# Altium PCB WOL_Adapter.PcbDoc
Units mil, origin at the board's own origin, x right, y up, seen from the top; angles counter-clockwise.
Board outline 2890 x 2280 mil, 4 copper layers (Top Layer, Mid-Layer 1, Mid-Layer 2, Bottom Layer), stack 37.4 mil thick; 48 components, 33 nets, 119 pads, 42 vias.
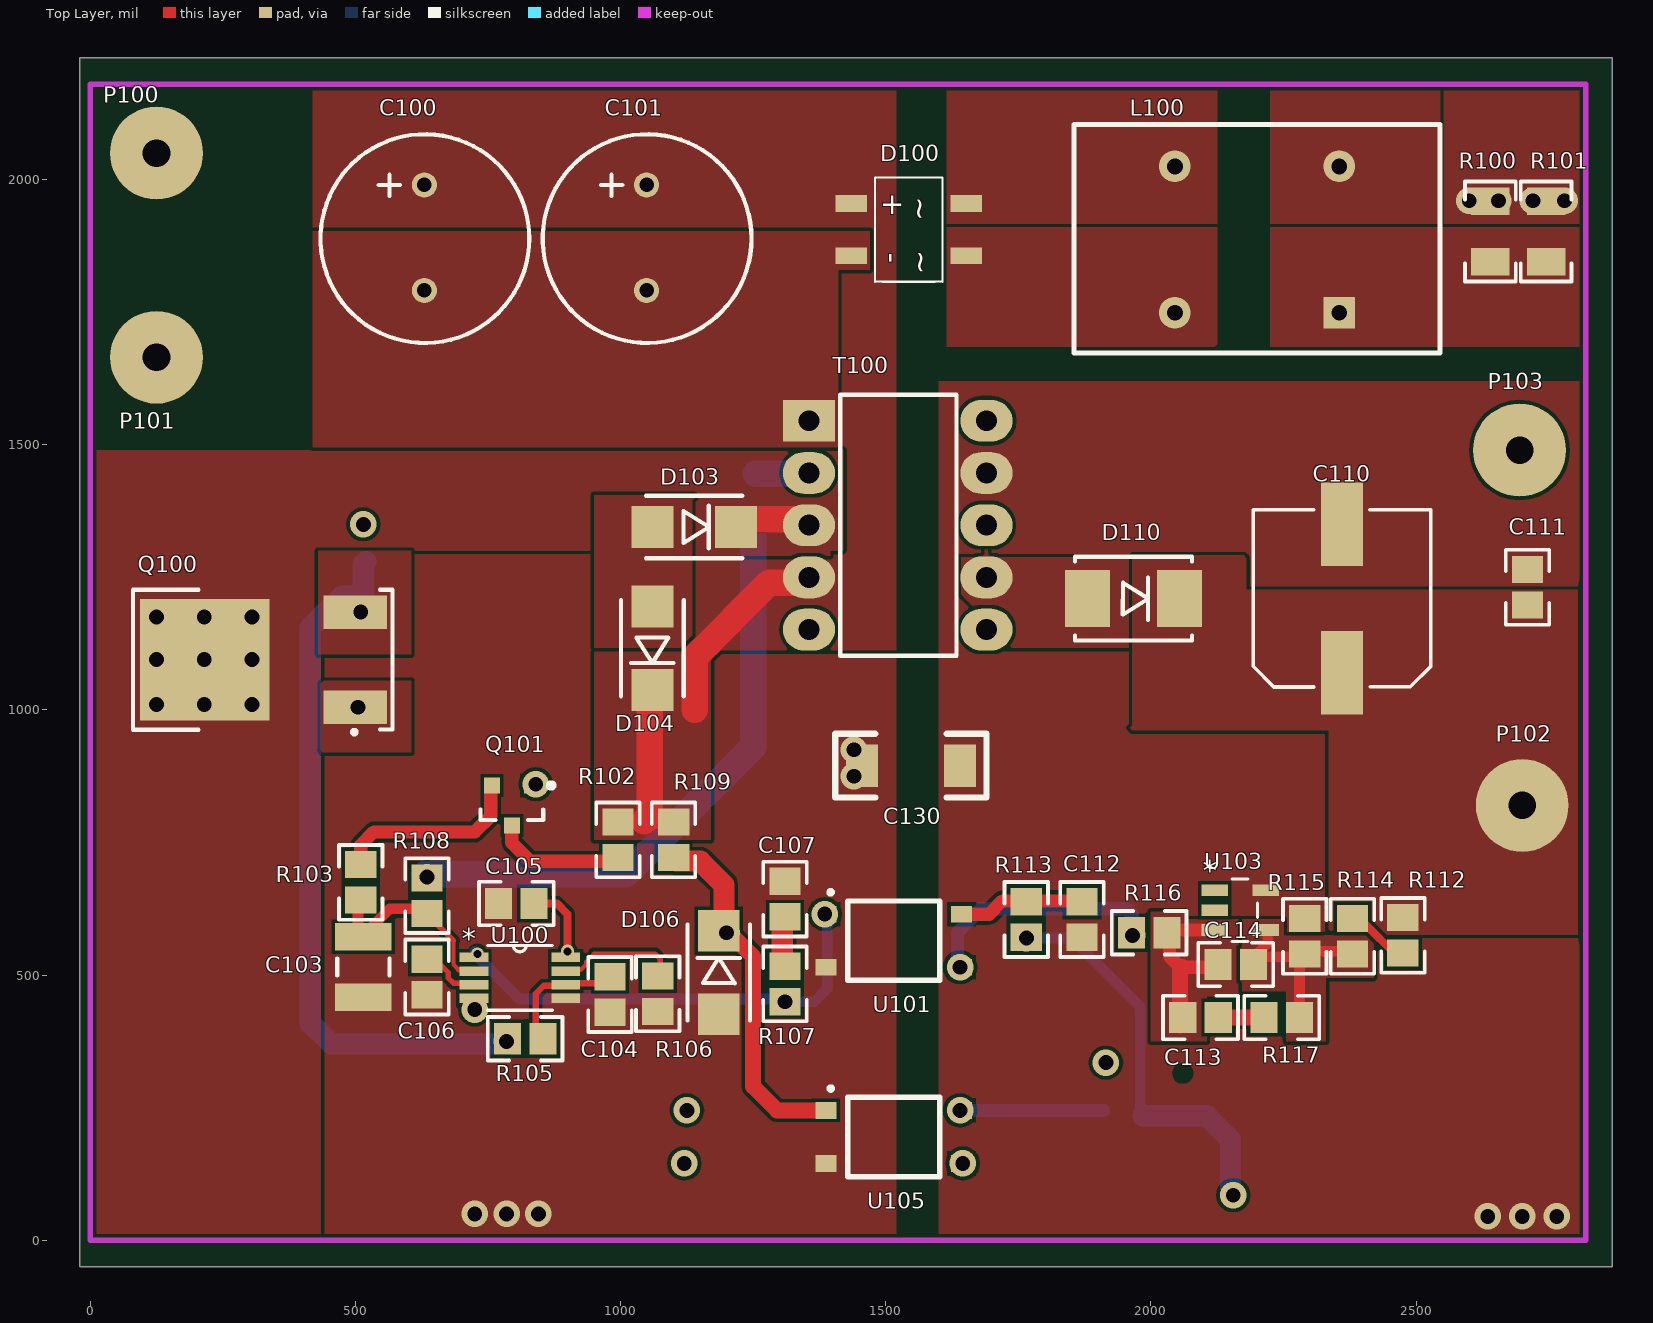
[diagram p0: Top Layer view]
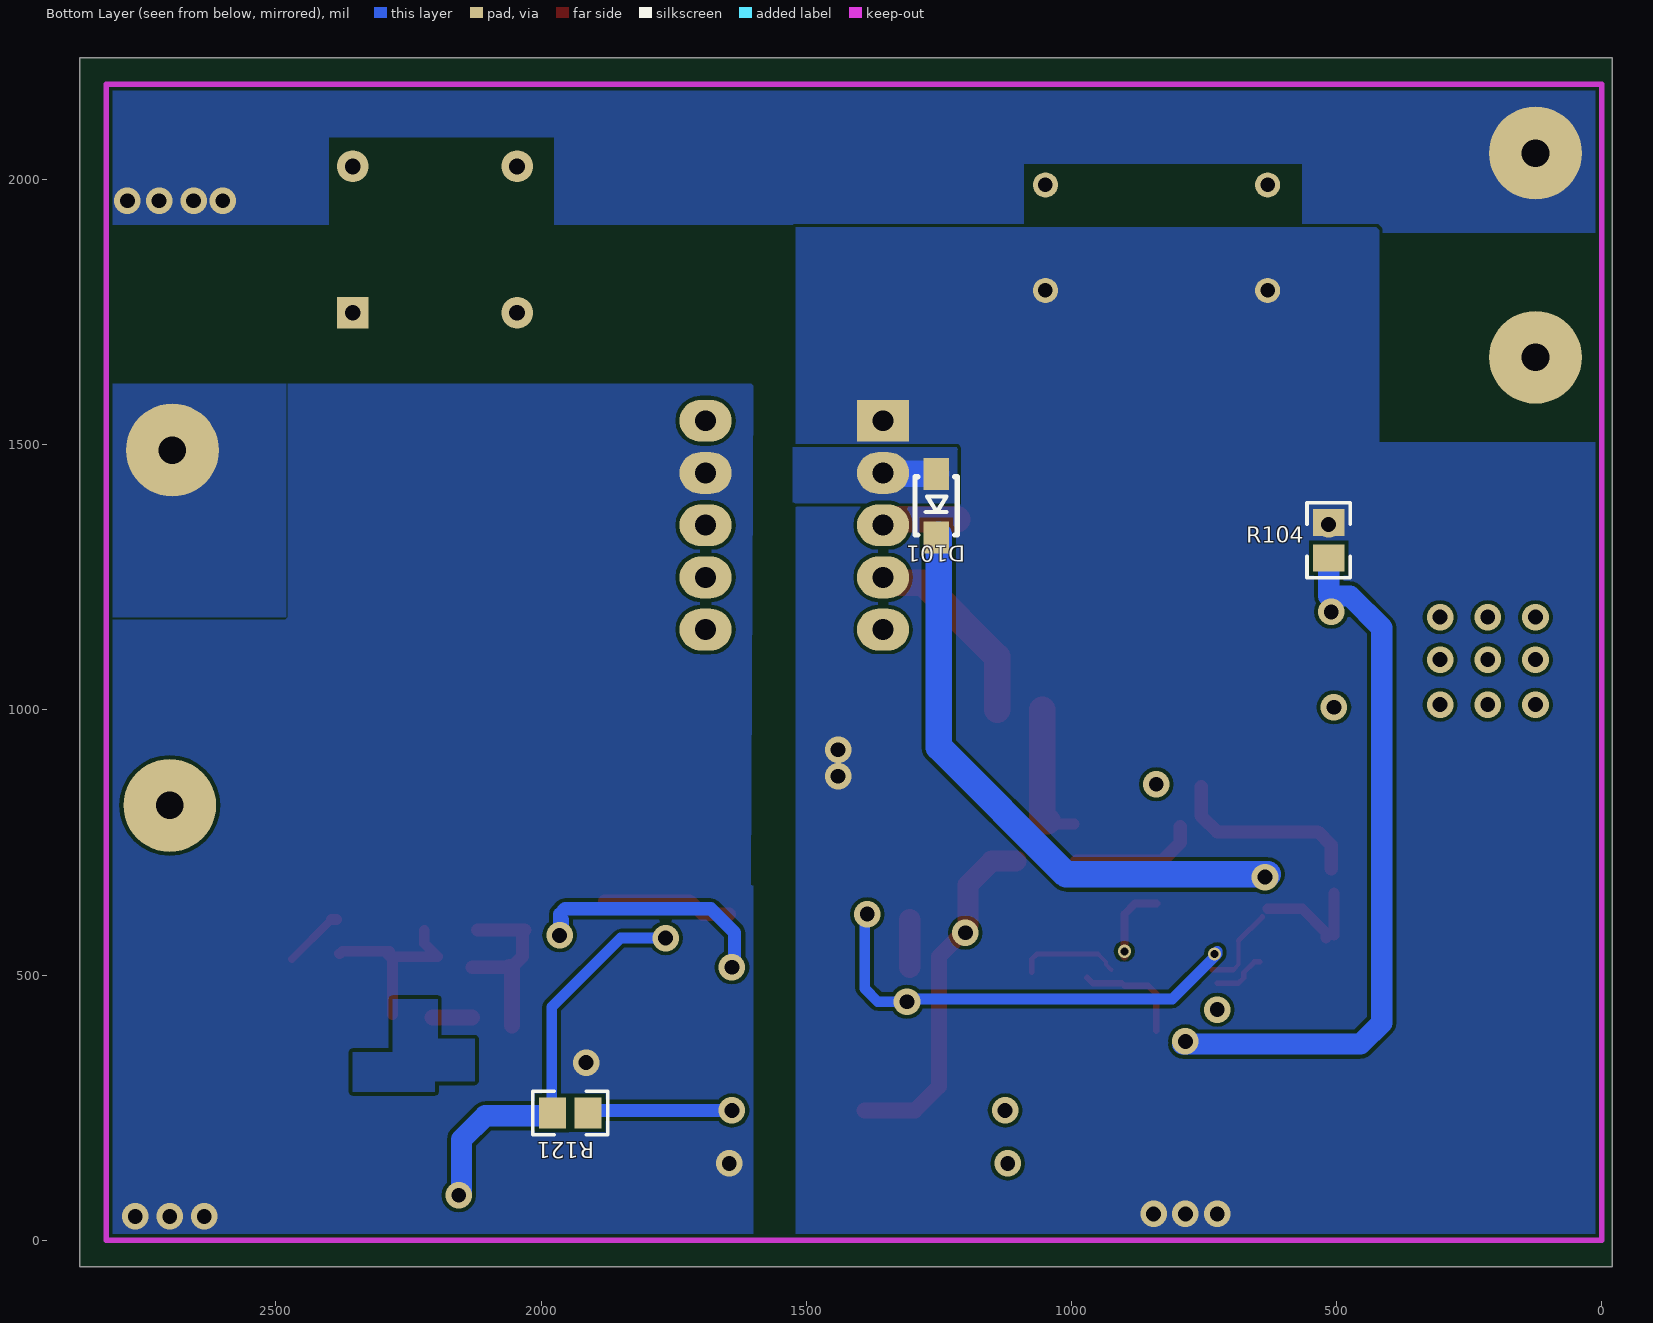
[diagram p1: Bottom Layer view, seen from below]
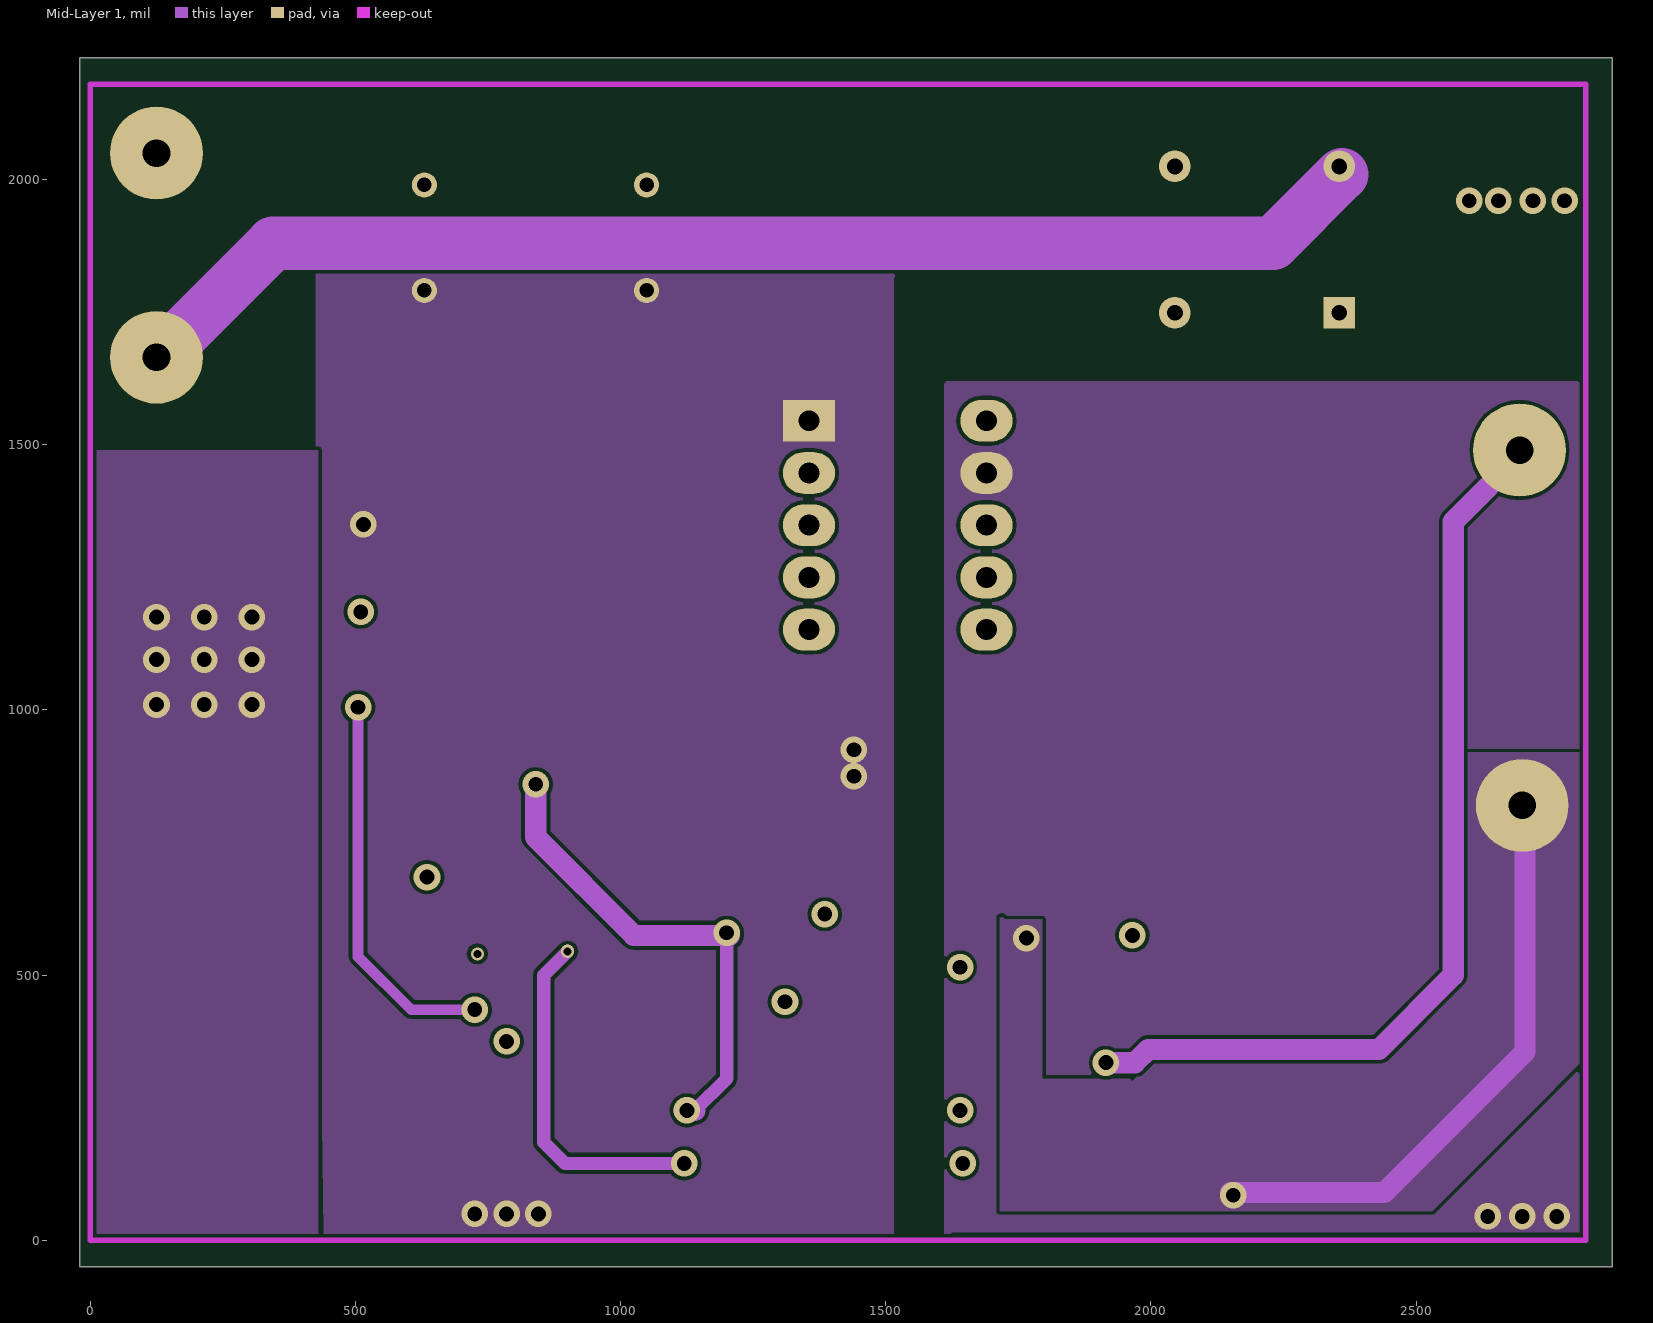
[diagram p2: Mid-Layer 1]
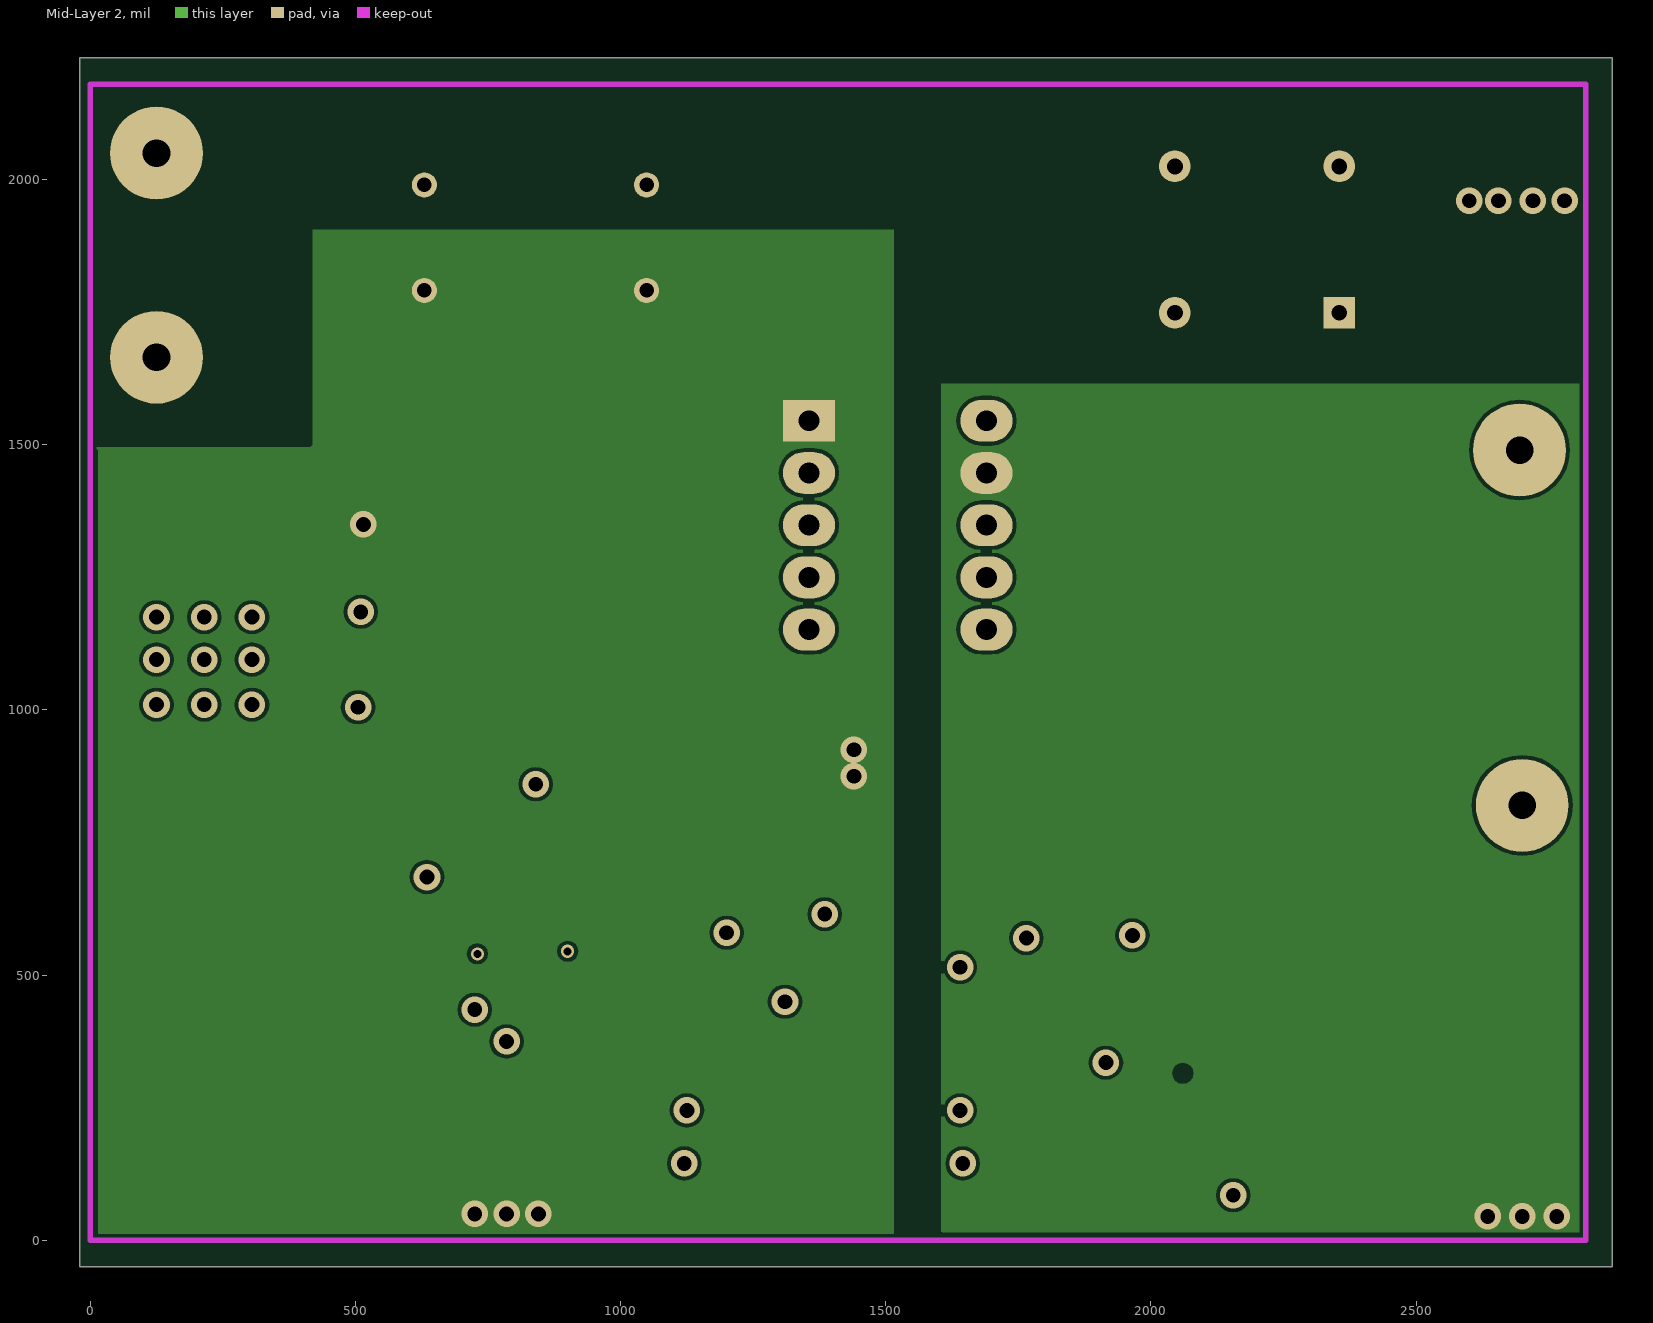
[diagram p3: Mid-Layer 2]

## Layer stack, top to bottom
Top Layer: signal copper 2
Dielectric: prepreg 6, FR-4, Dk 4.8
Mid-Layer 1: signal copper 1.4
Dielectric: prepreg 12.6, FR-4, Dk 4.8
Mid-Layer 2: signal copper 1.4
Dielectric: core 12.6, FR-4, Dk 4.8
Bottom Layer: signal copper 1.4

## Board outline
-20,-50 2870,-50 2870,2230 -20,2230

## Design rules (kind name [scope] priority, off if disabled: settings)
Clearance [All] p1: gap=7
Clearance U100 [(InComponent('U100'))] p2: gap=7
ComponentClearance [All] p1: gap=10 collisioncheckmode=3 verticalgap=10
ComponentClearance ComponentClearance_1 [All] p2: gap=10 collisioncheckmode=0 verticalgap=10
DiffPairsRouting DiffPairsRouting_1 [All] p2: maxlimit=10 minlimit=10 mostfreqgap=10 maxuncoupledlength=500
FanoutControl Fanout_LCC [IsLCC] p1: bgadir=Out bgaviamode=Centered fanoutstyle=Auto fanoutdirection=Alternating viagrid=1 // Fanout_LCC (Default Rule)
FanoutControl Fanout_BGA [IsBGA] p2: bgadir=Out bgaviamode=Centered fanoutstyle=Auto fanoutdirection=Alternating viagrid=1 // Fanout_BGA (Default Rule)
FanoutControl Fanout_Default [All] p4: bgadir=Out bgaviamode=Centered fanoutstyle=Auto fanoutdirection=Alternating viagrid=1 // Fanout_Default (Default Rule)
FanoutControl Fanout_Small [(CompPinCount < 5)] p5: bgadir=Out bgaviamode=Centered fanoutstyle=Auto fanoutdirection=OutThenIn viagrid=1 // Fanout_Small (Default Rule)
FanoutControl Fanout_BGA_1 [IsBGA] p6: bgadir=Out bgaviamode=Centered fanoutstyle=Auto fanoutdirection=Alternating viagrid=1 // Fanout_BGA (Default Rule)
FanoutControl Fanout_LCC_1 [IsLCC] p7: bgadir=Out bgaviamode=Centered fanoutstyle=Auto fanoutdirection=Alternating viagrid=1 // Fanout_LCC (Default Rule)
FanoutControl Fanout_SOIC_1 [IsSOIC] p8: bgadir=Out bgaviamode=Centered fanoutstyle=Auto fanoutdirection=Alternating viagrid=1 // Fanout_SOIC (Default Rule)
FanoutControl Fanout_Small_1 [(CompPinCount < 5)] p9: bgadir=Out bgaviamode=Centered fanoutstyle=Auto fanoutdirection=OutThenIn viagrid=1 // Fanout_Small (Default Rule)
FanoutControl Fanout_Default_1 [All] p10: bgadir=Out bgaviamode=Centered fanoutstyle=Auto fanoutdirection=Alternating viagrid=1 // Fanout_Default (Default Rule)
Height Height_1 [All] p2: minheight=0 maxheight=1000 prefheight=500
HoleSize [All] p1: absolutevalues=TRUE maxlimit=251 minlimit=8 maxpercent=80.000 minpercent=20.000
HoleSize HoleSize_1 [All] p2: absolutevalues=TRUE maxlimit=100 minlimit=1 maxpercent=80.000 minpercent=20.000
LayerPairs LayerPairs_1 [All] p2: enforce=TRUE
MinimumAnnularRing [All] p1: minimumring=5
PasteMaskExpansion PasteMaskExpansion_1 [All] p2: expansion=0
PlaneClearance PlaneClearance_1 [All] p2: clearance=20
PolygonConnect [All] p1: connectstyle=Direct reliefconductorwidth=8 reliefentries=4 polygonreliefangle="90 Angle"
PolygonConnect PolygonConnect_1 [All] p2: connectstyle=Relief reliefconductorwidth=10 reliefentries=4 polygonreliefangle="90 Angle"
RoutingPriority RoutingPriority_1 [All] p2: routingpriority=0
RoutingTopology RoutingTopology_1 [All] p2: topology=Shortest
RoutingVias [All] p1: holewidth=25 width=15 viastyle="Through Hole" minholewidth=5 minwidth=5 maxholewidth=28 maxwidth=50
ShortCircuit ShortCircuit_1 [All] p2: allowed=FALSE
SolderMaskExpansion [All] p1: expansion=3
SolderMaskExpansion SolderMaskExpansion_1 [All] p2: expansion=4
TestPointUsage [All] p1: valid=0 allowmultiple=FALSE
TestPointUsage TestPointUsage_1 [All] p2: valid=0 allowmultiple=FALSE
Testpoint [All] p1: side=15 testpointundercomponent=TRUE minsize=40 maxsize=100 preferedsize=60 minholesize=0 maxholesize=40 preferedholesize=32 testpointgrid=1 style=1023 order=0-112345678
Testpoint Testpoint_1 [All] p2: side=15 testpointundercomponent=TRUE minsize=40 maxsize=100 preferedsize=60 minholesize=0 maxholesize=40 preferedholesize=32 testpointgrid=1 style=1023 order=0-112345678
UnRoutedNet UnRoutedNet_1 [All] p2:
Width [All] p1: maxlimit=100 minlimit=8 preferedwidth=8 minimp=50.000000 maximp=50.000000 favimp=50.000000
13 further rules are at their usual default settings.

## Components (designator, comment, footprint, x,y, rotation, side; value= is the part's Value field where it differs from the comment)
C100 "UVR2W4R7MPD" "10mm th cap" 631,1810 r90 top
C101 "UVR2W4R7MPD" "10mm th cap" 1050,1810 r90 top
C103 "C3225X7R1E106M" 1210 515,515.39 r270 top
C104 "C2012X7R1H102K" 0805 980,463.46 r270 top
C105 "C2012X7R2A223K" 0805 803.46,635 r180 top
C106 "C2012X5R1E105K" 0805 635,496.54 r270 top
C107 "CC0805KRX7R9BB273" 0805 1310,643.46 r90 top
C110 "EEV-FK0J471P" SM_RADIAL_F 2360,1210.24 r270 top
C111 "C2012X5R0J226M" 0805 2710,1231.54 r90 top
C112 "C2012X7R1E474K" 0805 1870,605 r270 top
C113 "GRM21BR71H473KA01L" 0805 2093.46,420 r180 top
C114 "GQM2195C1H101JB01D" 0805 2160,520 r180 top
C130 "1000pF" 1808 1455,895 r0 top
D100 "DIODE-BRIDGE1" bridge 1435,1955 r0 top
D101 "1N4148W-7-F" SOD-123 1255,1385 r270 bottom
D103 "CMZ5938B" SMA 1138.74,1345 r0 top
D104 "10MQ100NTRPBF" SMA 1060,1116.26 r270 top
D106 "36V" SMA 1185,505 r90 top
D110 "B2100-13" SMB 1967.01,1210 r0 top
L100 "CM CHOKE" BU9S 2355,1749 r180 top
P100 "LIVE" PAD175#1 125,2050 r0 top
P101 "NEUTRAL" PAD175#2 125,1635 r0 top
P102 "Vout+" PAD175#1 2700,820 r0 top
P103 "Vout-" PAD175#1 2695,1490 r0 top
Q100 "SPD06N80C3" DPAK 304.33,1094.76 r180 top
Q101 "Manufacturer_PN" sot-23 795,820 r270 top
R100 "CRCW1206-20R0FRT1" 1206 2640,1902.09 r90 top
R101 "CRCW1206-20R0FRT1" 1206 2745,1902.09 r90 top
R102 "CRCW08051M00FKEA" 0805 995,755 r270 top
R103 "CRCW0805200kFKEA" 0805 510,675 r270 top
R104 "CRCW08052R21FNEA" 0805 515,1320 r90 bottom
R105 "CRCW0805499RFKEA" 0805 820,380 r0 top
R106 "CRCW080582k5FKEA" 0805 1070,465 r270 top
R107 "CRCW08051k00FKEA" 0805 1310,483.46 r90 top
R108 "CRCW080530R1FKEA" 0805 635,650 r270 top
R109 "CRCW080510M0FKEA" 0805 1100,755 r270 top
R112 "CRCW080549R9FKEA" 0805 2475,575 r270 top
R113 "CRCW080510R0FKEA" 0805 1765,605 r90 top
R114 "CRCW080563k4FKEA" 0805 2380,573.46 r270 top
R115 "CRCW080520k5FKEA" 0805 2290,573.46 r90 top
R116 "CRCW0805499RFKEA" 0805 1996.54,580 r0 top
R117 "CRCW0805499RFKEA" 0805 2246.54,420 r0 top
R121 "CRCW080510k0FKEA" 0805 1945,240 r180 bottom
T100 "XFMR-PA2685NL" PA2685NL 1355,1545.28 r0 top
U100 "LM5021MM" MUA08A 810,495 r0 top
U101 "PS2501L-1H" FOD121 1515,565 r0 top
U103 "LMV431M5" MF05A 2168,622.5 r0 top
U105 "FODM121" FOD121 1515,195 r0 top

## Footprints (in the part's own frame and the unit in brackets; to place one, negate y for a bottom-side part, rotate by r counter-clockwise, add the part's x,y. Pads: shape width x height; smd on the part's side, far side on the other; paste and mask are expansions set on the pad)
"10mm th cap" [mm]
  round 1.2 hole 0.7: 1(4.572,0.025) 2(-0.483,0.025)
  silkscreen extent -3,-5 7,5
0805 [mm] "0805 from SM-752 data"
  rect 1.3x1.5 smd: 1(-0.85,0) 2(0.85,0)
  silkscreen extent -1.79,-1.04 1.79,1.04, body extent -1.1,-0.72 1.1,0.72, height 1.1
1206 [mm] "1206 from SM-752 data"
  rect 1.3x1.85 smd: 1(-1.45,0) 2(1.45,0)
  silkscreen extent -2.39,-1.22 2.39,1.22, body extent -1.7,-0.9 1.7,0.9, height 1.35
1210 [mm] "1210 from SM-752 data"
  rect 1.3x2.7 smd: 1(-1.45,0) 2(1.45,0)
  silkscreen extent -0.4,-1.25 0.4,1.25, body extent -1.7,-1.35 1.7,1.35, height 1.35
1808 [mil]
  rect 60x80 smd: 1(0,0) 2(185,0)
  silkscreen extent -50,-60 235,60
bridge [mm]
  rect 1.5x0.8 smd: 1(0,0) 2(0,-2.5) 3(5.5,-2.5) 4(5.5,0)
  silkscreen extent 1.14,-3.76 4.37,1.25
BU9S [mil]
  rect 60x60 hole 30: 1(0,0)
  round 60 hole 30: 2(0,-276) 3(310,-276) 4(310,0)
  silkscreen extent -190,-355 500,76
DPAK [mm] "D-PAK, 3-Pads, Body 6.2x6.7mm (max), IPC Medium Density_modified 2008-05-02 to match OnSemi land pattern"
  rect 3.05x1.6 smd: 1(-4.97,2.28) 3(-4.97,-2.28)
  rect 6.2x5.8 smd: 4(2.25,0)
  silkscreen extent -6.75,-3.35 5.68,3.55, body extent -2.1,-3.35 4.1,3.35, height 2.39
FOD121 [mm] "Fairchild OptoCoupler"
  rect 1x0.8 smd: 1(-3.25,1.27) 2(-3.25,-1.27) 3(3.25,-1.27) 4(3.25,1.27)
  silkscreen extent -3.1,-1.9 2.2,2.39, body extent -3.85,-2.03 3.85,2.03, height 2.3
MF05A [mil]
  rect 50x22 smd: 1(-48,37.5) 2(-48,0) 3(-48,-37.5) 4(48,-37.5) 5(48,37.5)
  silkscreen extent -15,-59 33,59
MUA08A [mil]
  rect 54x18 smd: 1(-86.5,38.39) 2(-86.5,12.8) 3(-86.5,-12.8) 4(-86.5,-38.39) 5(86.5,-38.39) 6(86.5,-12.8) 7(86.5,12.8) 8(86.5,38.39)
  silkscreen extent -61,-61 61,61
PA2685NL [mm] "Pulse PA2685"
  rect 2.5x2 hole 1: 1(0,0)
  oval 2.5x2 hole 1: 2(0,-2.5) 3(0,-5) 4(0,-7.5) 5(0,-10) 6(8.5,-10) 7(8.5,-7.5) 8(8.5,-5) 9(8.5,-2.5) 10(8.5,0)
  silkscreen extent 1.5,-11.25 7.07,1.25
PAD175#1 [mil]
  round 175 hole 52: 1(0,0)
PAD175#2 [mil]
  round 175 hole 52: 1(0,30)
SM_RADIAL_F [mm] "Panasonic F"
  rect 4x2 smd: 1(3.55,0) 2(-3.55,0)
  silkscreen extent -4.25,-4.25 4.24,4.25
SMA [mm] "Molded Diode, 2-Leads, Body 4.3x2.6mm, IPC Medium Density, based on OnSemi component dimensions and land pattern"
  rect 2x2 smd: 1(-2,0) 2(2,0)
  silkscreen extent -2.3,-1.5 2.3,1.5, body extent -2.29,-1.46 2.28,1.46, height 2.27
SMB [mil] "Molded Diode, 2-Leads, Body 5.4x3.6mm, IPC Medium Density, based on OnSemi component dimensions"
  rect 85x107.99 smd: 1(-87.01,0) 2(87.01,0)
  silkscreen extent -110,-79 110,79, body extent -110,-78 110,78, height 96
SOD-123 [mil]
  rect 60x48 smd: 1(-60,0) 2(60,0)
  silkscreen extent -55,-40 55,40
sot-23 [mm] "SOT23, 3-Leads, Body 3.0x2.6mm (max), Pitch 0.95mm, IPC Medium Density, from National MF03A"
  rect 0.76x0.76 smd: 1(-0.955,0.953) 2(-0.955,-0.953) 3(0.955,0)
  silkscreen extent -1.08,-1.5 0.7,2.01, body extent -0.7,-1.52 0.7,1.52, height 1.12

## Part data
C100 C101: library part WB_CAP_POLARIZED, "Polarized Capacitor"
C103 C104 C105 C106 C107 C111 C112 C113 C114: "Capacitor"
C110: "Polarized Capacitor"
C130: library part CAP-1808, "Capacitor Ceramic X7R"
D100: "Diode Bridge"
D101 D110: "Schottky Diode"
D103 D106: library part WB_Zener
D104: library part WB_DIODE, "Diode"
L100: library part "IND-COMMON MODE CHOKE", "coil craft common mode choke"
P100 P101 P102 P103: library part PAD175, "TEST POINT"
Q101: library part MMBTA42, "NPN Transistor"
R100 R101 R102 R103 R104 R105 R106 R107 R108 R109 R112 R113 R114 R115 R116 R117 R121: "Resistor"
T100: library part XFMR-PA1407, "POE TRANSFORMER"
U100: library part LM5021MM-1, "AC-DC Current Mode PWM Controller"
U101 U105: "Full Pitch Mini-Flat Package Transistor Output  Optocoupler"
U103: library part LMV431IM5, "Low-Voltage (1.24V) Adjustable Precision Shunt Regulators"

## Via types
v1: diameter 50, hole 28, Top Layer to Bottom Layer, 40 vias
v2: diameter 25, hole 15, Top Layer to Bottom Layer, 2 vias

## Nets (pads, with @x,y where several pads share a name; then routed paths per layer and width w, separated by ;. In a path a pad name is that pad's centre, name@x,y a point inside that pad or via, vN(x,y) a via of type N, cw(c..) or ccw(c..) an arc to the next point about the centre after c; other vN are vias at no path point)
GND: C100.2 C101.2 C103.2 C104.2 C105.2 C106.2 C107.2 C130.1 D100.2 D106.1 R104.2 R106.2 T100.1 U100.5 U101.2 U105.2
  other v1: 725,50 785,50 845,50 1440,875 1440,925 515,1350
NetC100_1: C100.1 C101.1 D100.1 D104.2 R102.1 R109.1 T100.4 | length 702.1
  Top Layer w20: R102.1@995,785 R109.1@1100,785
  Top Layer w50: 1045,790 1055,800 D104.2@1055,1000 ; 1140,1000 1140,1100 1280,1240 T100.4@1365,1240
NetC103_1: C103.1 R103.2 R108.2 U100.2 | length 381.4
  Top Layer w8: 685,565 685,520 695,510
  Top Layer w10: R108.2@640,610 685,565 ; 695,510 U100.2@735,510
  Top Layer w20: C103.1@505,575 R103.2@505,655 ; C103.1@520,570 520,580 565,625 R108.2@630,625
NetC104_1: C104.1 R105.2 U100.6 | length 205.4
  Top Layer w12: R105.2@840,395 840,465 855,480 U100.6@900,480 ; U100.6@905,485 960,485 C104.1@970,495
NetC105_1: C105.1 U100.8 | length 808.5
  Top Layer w15: C105.1@840,635 880,635 900,615 U100.8@900,535
  Mid-Layer 1 w25: v2(900,545) 855,500 855,185 895,145 v1(1120,145)
NetC106_1: C106.1 U100.3 | length 102.4
  Top Layer w10: C106.1@645,525 655,525 675,505 675,495 685,485 U100.3@725,485
NetC107_1: C107.1 R107.2 | length 90
  Top Layer w40: R107.2@1305,515 C107.1@1305,605
NetC110_1: C110.1 C111.1 D110.2 P102.1 R112.1 R113.1 R121.1 | length 1942.3
  Mid-Layer 1 w40: v1@2150,90 2440,90 2705,355 P102.1@2705,820
  Bottom Layer w15: R121.1@1975,240 2035,240
  Bottom Layer w20: v1(1765,570) 1850,570 1980,440 R121.1@1980,240
  Bottom Layer w40: R121.1@1985,235 2105,235 2150,190 v1@2150,90
  other v1: 2155,85
NetC112_1: C112.1 R113.2 U101.4 | length 252.4
  Top Layer w25: U101.4@1645,615 1695,615 1720,640 C112.1@1880,640 ; R113.2@1760,635 R113.2@1765,630
NetC113_1: C113.1 R117.1 | length 75
  Top Layer w30: C113.1@2130,420 R117.1@2205,420
NetC113_2: C113.2 C114.2 R116.2 U103.3 | length 345.4
  Top Layer w25: R116.2@2030,585 U103.3 ; R116.2@2035,575 2035,535 2055,515 C114.2@2130,515
  Top Layer w30: C113.2@2055,405 2055,510 2060,515
NetC114_1: C114.1 R114.2 R115.1 R117.2 U103.4 | length 366.6
  Top Layer w20: U103.4@2220,585 2220,560 2195,535 R115.1@2285,535 ; R117.2@2280,425 2280,530 R115.1 ; R115.1@2285,545 2375,545 R114.2
NetD100_3: D100.3 L100.4
NetD100_4: D100.4 L100.3
NetD101_1: D101.1 T100.2 | length 105
  Bottom Layer w50: D101.1 T100.2@1360,1445
NetD101_2: D101.2 R108.1 | length 1119.4
  Bottom Layer w50: v1@630,690 1010,690 1250,930 D101.2@1250,1330
  other v1: 635,685
NetD103_1: D103.1 D104.1
NetD103_2: D103.2 Q100.4 T100.3 | length 151.2
  Top Layer w50: D103.2@1215,1360 1345,1360 T100.3@1360,1345
  other v1: 125,1010 215,1010 305,1010 125,1095 215,1095 305,1095 125,1175 215,1175 305,1175
NetD106_2: D106.2 Q101.1 R109.2 U105.1 | length 1567.4
  Top Layer w30: D106.2@1205,580 1250,535 1250,290 1295,245 U105.1@1390,245
  Top Layer w40: R109.2@1105,715 1150,715 1195,670 D106.2@1195,595
  Mid-Layer 1 w25: v1@1140,245 1200,305 v1@1200,570
  Mid-Layer 1 w40: v1@840,865 840,760 1025,575 v1@1205,575 ; v1@1120,245 v1@1140,245
  other v1: 1125,245 1200,580 840,860
NetD110_1: D110.1 T100.7
NetL100_1: L100.1 R100.1 R101.1
NetL100_2: L100.2 P101.1 | length 2404.1
  Mid-Layer 1 w100: P101.1@115,1640 115,1650 345,1880 2230,1880 L100.2@2360,2010
NetP100_1: P100.1 R100.2 R101.2
  other v1: 2600,1960 2655,1960 2720,1960 2780,1960
NetQ100_1: Q100.1 U100.4 | length 741.4
  Mid-Layer 1 w20: v1@505,1010 505,535 605,435 v1@730,435
  other v1: 725,435 505,1005
NetQ100_3: Q100.3 R104.1 R105.1 | length 1328.5
  Bottom Layer w40: R104.1@520,1280 515,1275 515,1215 475,1215 415,1155 415,410 455,370 v1@790,370
  other v1: 785,375 510,1185
NetQ101_2: Q101.2 R103.1 | length 367.8
  Top Layer w25: R103.1@510,700 510,745 535,770 725,770 755,800 Q101.2@755,855
NetQ101_3: Q101.3 R102.2 | length 239.5
  Top Layer w25: Q101.3@795,780 795,750 830,715 R102.2@990,715
NetR106_1: R106.1 U100.7 | length 194.5
  Top Layer w8: 925,510 935,520 935,525 950,540
  Top Layer w10: 950,540 1065,540 1075,530 R106.1@1075,505
NetR107_1: R107.1 U100.1 U101.1 | length 855.6
  Bottom Layer w20: v2@725,545 725,540 810,455 v1@1310,455 ; v1(1310,450) 1365,450 1390,475 v1@1390,615
  other v1: 1385,615
  other v2: 730,540
NetR112_2: R112.2 R114.1 | length 116.1
  Top Layer w15: R114.1@2395,605 R112.2@2470,530
  Top Layer w20: R114.1@2385,605 R114.1@2395,605
NetR116_1: R116.1 U101.3 | length 487.8
  Bottom Layer w25: v1@1635,515 1635,580 1680,625 1955,625 1965,615 v1(1965,575) ; v1@1960,575 1960,605
  other v1: 1640,515
NetR121_2: R121.2 U105.4 | length 279.1
  Bottom Layer w25: v1@1635,235 1645,245 R121.2@1910,245
  other v1: 1640,245
RTN: C110.2 C111.2 C112.2 C130.2 P103.1 R115.2 T100.9 U103.5 U105.3 | length 1769.3
  Mid-Layer 1 w40: v1(1915,335) 1970,335 1995,360 2430,360 2570,500 2570,1355 P103.1@2705,1490
  other v1: 2635,45 2700,45 2765,45 1645,145
pads on no net: T100.5 T100.6 T100.8 T100.10 U103.1 U103.2

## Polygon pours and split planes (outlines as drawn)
GND on Top Layer "GND" (solid, remove dead copper, pour order 1017): 430,1305 430,10 1510,10 1520,0 1520,1105 955,1105 950,1110 950,1305 435,1305
RTN on Top Layer "RTN" (solid, remove dead copper, pour order 1001): 2815,580 2815,5 2810,0 1600,0 1600,1620 2815,1620 2815,1225 2810,1220 2800,1230 2180,1230 2180,1290 2175,1295 1635,1295 1635,1215 1645,1205 1665,1185 1665,1110 1965,1110 1970,1105 1965,1100 1965,965 2340,965 2345,960 2350,955 2350,580 2815,580
NetD110_1 on Top Layer "NetD110_1" (solid, remove dead copper, pour order 1020): 1635,1305 1635,1105 1965,1105 1970,1110 1975,1115 1975,1305 1640,1305
NetC113_2 on Top Layer "NetC113_2" (solid, remove dead copper, pour order 1000): 2000,610 2000,375 2105,375 2105,460 2165,460 2165,605 2065,605 2065,620 2000,620 2000,610
NetC114_1 on Top Layer "NetC100_1" (solid, remove dead copper, pour order 1001): 2170,605 2165,600 2165,470 2255,470 2255,375 2330,375 2330,495 2420,495 2420,575 2250,575 2250,605 2170,605 2165,600
NetL100_1 on Top Layer "NetL100_1" (solid, remove dead copper, pour order 1002): 2225,1910 2225,1685 2815,1685 2810.2,1689.69 2810.2,1910 2225,1910
NetD100_3 on Top Layer "NetD100_3" (solid, remove dead copper, pour order 1003): 1615,1910 1615,1685 2120.1,1685 2125,1689.79 2125,1910 1619.9,1910
NetD100_4 on Top Layer "NetD100_4" (solid, remove dead copper, pour order 1004): 1615,2170 2125,2170 2125,1905 2120.1,1910 1615,1910 1615,2165
NetL100_2 on Top Layer "NetL100_2" (solid, remove dead copper, pour order 1005): 2225,2170 2545,2170 2545,1910 2540.36,1915 2225,1915 2225,2170
NetP100_1 on Top Layer "NetP100_1" (solid, remove dead copper, pour order 1006): 2550,2175 2810,2175 2810,1910 2820,1900 2545,1900 2545,2175 2550,2175
NetC100_1 on Top Layer "NetC100_1" (solid, remove dead copper, pour order 1007): 420,2180 420,1910 1470,1910 1470,2185 1465,2180 420,2180
NetC100_1 on Top Layer "NetC100_1" (solid, remove dead copper, pour order 1008): 950,1110 950,755 1170,755 1170,1110 950,1110
NetD103_1 on Top Layer "NetD103_1" (solid, remove dead copper, pour order 1009): 950,1405 1145,1405 1135,1395 1135,1110 950,1110 950,1405
NetQ100_3 on Top Layer "NetQ100_3" (solid, remove dead copper, pour order 1010): 430,1300 605,1300 605,1105 430,1105 430,1315
NetQ100_1 on Top Layer "NetQ100_1" (solid, remove dead copper, pour order 1011): 440,1055 605,1055 605,920 430,920 435,925 435,1050 440,1055
GND on Top Layer "GND" (solid, remove dead copper, pour order 1014): 420,1905 1470,1905 1470,1830 1410,1830 1410,1490 1405,1495 420,1495 420,1905
NetD103_2 on Top Layer "NetD103_2" (solid, remove dead copper, pour order 1015): 5,1490.02 1425,1490.02 1430,1495 1395,1460.12 1395,1290.68 955,1290.68 945,1300.65 435,1300.65 435,4.98 430,0 0,0 0,1485.03 -5,1490.02
NetD103_2 on Top Layer "NetD103_2" (solid, remove dead copper, pour order 1016): 1290,1495 1420,1495 1420,1295 1415,1300 1300,1300 1300,1490 1295,1495
NetC100_1 on Top Layer "NetC100_1" (solid, remove dead copper, pour order 1018): 952.43,1110 952.43,760 957.45,755 1349.23,755 1349.23,1095 1354.25,1090 1520,1090 1520,2170 420.02,2170 420.02,1915 415,1910 420.02,1905 1474.8,1905 1474.8,1830 1414.52,1830 1414.52,1295 1404.48,1305 947.41,1305 947.41,1120
NetC110_1 on Top Layer "NetC110_1" (solid, remove dead copper, pour order 1000): 1960,1291.49 2175,1291.49 2180,1286.49 2180,1226.49 2805,1226.49 2805,576.49 2345,576.49 2335,586.49 2335,961.49 1965,961.49 1960,966.49 1965,971.49 1965,1286.49
RTN on Mid-Layer 1 "RTN" (solid, remove dead copper, pour order 1024): 1610,1615 1610,10 1615,5 1625,15 2815,15 2815,1610 2805,1620 1615,1620
NetC110_1 on Mid-Layer 1 "NetC100_1" (solid, remove dead copper, pour order 1000): 2595,920 2590,915 2590,490 2570,490 2430,350 2005,350 2005,340 1965,300 1960,305 1795,305 1795,405 1795,605 1725,605 1715,615 1715,105 1715,55 2450,55 2530,55 2715,240 2820,345 2820,920 2590,920
NetD103_2 on Mid-Layer 1 "D103_2" (solid, remove dead copper, pour order 1022): 0,1490 430,1490 430,10 435,5 5,5 5,1490 0,1495
GND on Mid-Layer 1 "GND" (solid, remove dead copper, pour order 1023): 440,10 425,25 425,1825 1515,1825 1520,1820 1515,1815 1515,5 435,5 430,10 420,20 420,1495
GND on Mid-Layer 2 "GND" (solid, remove dead copper, pour order 1025): 5,1495 415,1495 420,1500 420,1905 1515,1905 1515,5 10,5 5,0 15,10 15,1490
RTN on Mid-Layer 2 "RTN" (solid, remove dead copper, pour order 1026): 1605,1615 2810,1615 2810,15 1610,15 1600,5 1605,10 1605,1615
RTN on Bottom Layer "RTN" (solid, remove dead copper, pour order 1031): 1600,1615 1600,5 2815,5 2809.96,10 2809.96,1170 2482.26,1170 2477.22,1175 2477.22,1615 1600,1615 1600,675 1605.04,670
NetD101_1 on Bottom Layer "NetD101_!" (solid, remove dead copper, pour order 1027): 1210,1495 1215.08,1490 1215.08,1390 1519.92,1390 1525,1385 1525,1495 1210,1495
GND on Bottom Layer "GND" (solid, remove dead copper, pour order 1028): 5,1505 420,1505 420,1905 425,1910 1520,1910 1520,5 5,5 5,1500 10,1505
RTN on Bottom Layer "RTN" (solid, remove dead copper, pour order 1029): 2480,1615 2480,1175 2810,1175 2815,1180 2815,1615 2475,1615
no net on Bottom Layer "NetC122_1" (solid, remove dead copper, pour order 1030): 2125,305 2125,380 2195,380 2195,455 2280,455 2280,355 2355,355 2355,280 2200,280 2200,300 2125,300 2125,305
NetP100_1 on Bottom Layer "NetP100_1" (solid, remove dead copper, pour order 1032): -5,2180 -5,1910 5,1900 565,1900 565,2030 1090,2030 1090,1915 1095,1910 1100,1915 1975,1915 1975,2080 2400,2080 2400,1915 2815,1915 2815,2180 2810,2175 0,2175

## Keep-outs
Keep-Out Layer:
  lines w10: 0,0 0,2180 2820,2180 2820,0 0,0

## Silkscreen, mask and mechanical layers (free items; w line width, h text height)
M16 Title Block:
  drawing of 24 lines, arcs and shapes, not listed

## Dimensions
0,0 to 0,2180 on M1 Board Outline
0,-15 to 2820,0 on M1 Board Outline
-20,-50 to 2870,-50 on M2 Board Dimensions
-20,-50 to -20,2230 on M2 Board Dimensions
